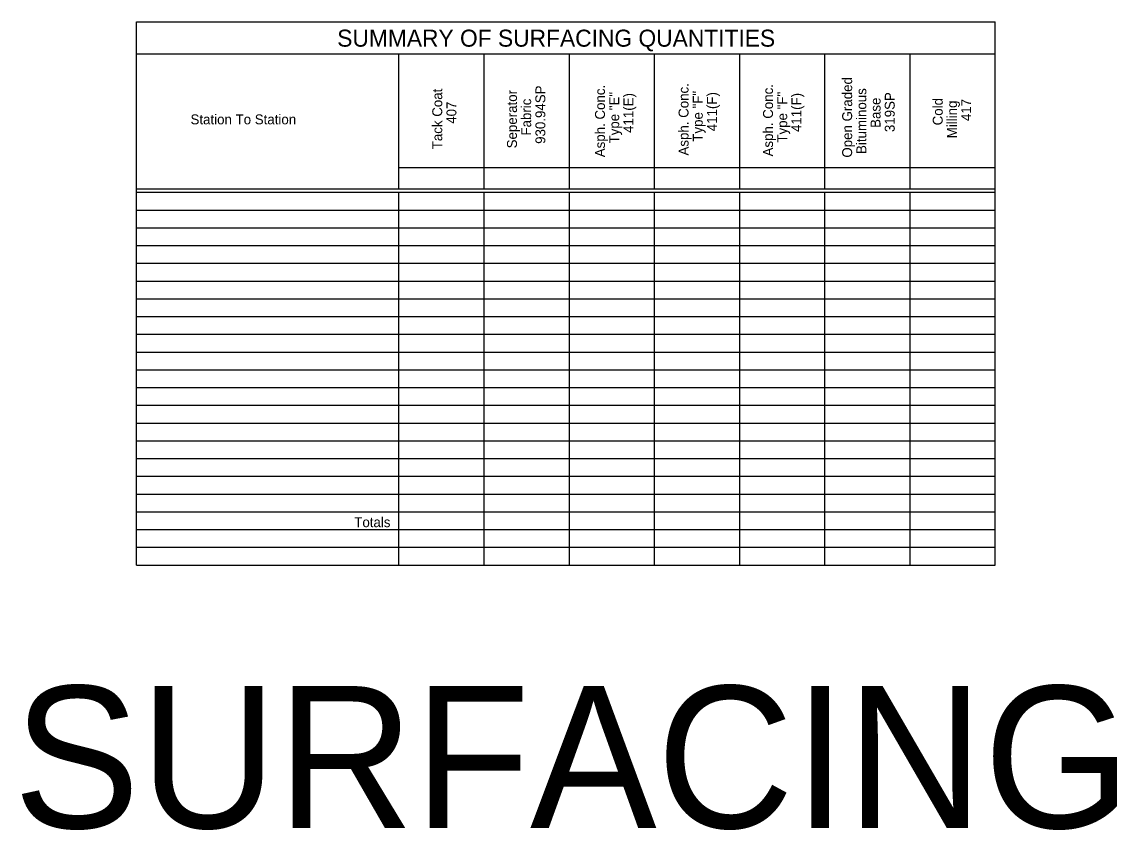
# Model space of a CAD drawing. Extents: x 1790274 to 1791453, y 1790011 to 1790884.
# Drawn here: x 1791298.7 to 1791452.9, y 1790276.5 to 1790390.3 of the extents above; entities that cross this region are included whole.
import ezdxf

# ---------------------------------------------------------------- set-up
doc = ezdxf.new("R2010")
doc.units = 0
doc.layers.add('Level 1', color=7, linetype='Continuous')
doc.layers.add('Level 2', color=7, linetype='Continuous')

msp = doc.modelspace()

# ---------------------------------------------------------------- linework, layer by layer
at = {"layer": 'Level 1'}
for p, q in [((1791314.78, 1790390.3), (1791435.78, 1790390.3)), ((1791314.78, 1790313.8), (1791314.78, 1790390.3)), ((1791435.78, 1790313.8), (1791435.78, 1790390.3)), ((1791314.78, 1790385.8), (1791435.78, 1790385.8)), ((1791351.78, 1790366.8), (1791351.78, 1790385.8)), ((1791363.78, 1790366.8), (1791363.78, 1790385.8)), ((1791375.78, 1790366.8), (1791375.78, 1790385.8)), ((1791387.78, 1790366.8), (1791387.78, 1790385.8)), ((1791399.78, 1790366.8), (1791399.78, 1790385.8)), ((1791411.78, 1790366.8), (1791411.78, 1790385.8)), ((1791423.78, 1790366.8), (1791423.78, 1790385.8)), ((1791351.78, 1790369.8), (1791435.78, 1790369.8)), ((1791314.78, 1790366.8), (1791435.78, 1790366.8)), ((1791314.78, 1790366.3), (1791435.78, 1790366.3)), ((1791351.78, 1790313.8), (1791351.78, 1790366.3)), ((1791363.78, 1790313.8), (1791363.78, 1790366.3)), ((1791375.78, 1790313.8), (1791375.78, 1790366.3)), ((1791387.78, 1790313.8), (1791387.78, 1790366.3)), ((1791399.78, 1790313.8), (1791399.78, 1790366.3)), ((1791411.78, 1790313.8), (1791411.78, 1790366.3)), ((1791423.78, 1790313.8), (1791423.78, 1790366.3)), ((1791314.78, 1790363.8), (1791435.78, 1790363.8)), ((1791314.78, 1790361.3), (1791435.78, 1790361.3)), ((1791314.78, 1790358.8), (1791435.78, 1790358.8)), ((1791314.78, 1790356.3), (1791435.78, 1790356.3)), ((1791314.78, 1790353.8), (1791435.78, 1790353.8)), ((1791314.78, 1790351.3), (1791435.78, 1790351.3)), ((1791314.78, 1790348.8), (1791435.78, 1790348.8)), ((1791314.78, 1790346.3), (1791435.78, 1790346.3)), ((1791314.78, 1790343.8), (1791435.78, 1790343.8)), ((1791314.78, 1790341.3), (1791435.78, 1790341.3)), ((1791314.78, 1790338.8), (1791435.78, 1790338.8)), ((1791314.78, 1790336.3), (1791435.78, 1790336.3)), ((1791314.78, 1790333.8), (1791435.78, 1790333.8)), ((1791314.78, 1790331.3), (1791435.78, 1790331.3)), ((1791314.78, 1790328.8), (1791435.78, 1790328.8)), ((1791314.78, 1790326.3), (1791435.78, 1790326.3)), ((1791314.78, 1790323.8), (1791435.78, 1790323.8)), ((1791314.78, 1790321.3), (1791435.78, 1790321.3)), ((1791314.78, 1790318.8), (1791435.78, 1790318.8)), ((1791314.78, 1790316.3), (1791435.78, 1790316.3)), ((1791314.78, 1790313.8), (1791435.78, 1790313.8))]:
    msp.add_line(p, q, dxfattribs=at)

# ---------------------------------------------------------------- texts
at = {"layer": 'Level 2'}
for s, height, p in [('SUMMARY OF SURFACING QUANTITIES', 2.4, (1791343.08, 1790386.81)), ('Station To Station', 1.4, (1791322.41, 1790375.87)), ('Totals', 1.4, (1791345.48, 1790319.13)), ('SURFACING', 20, (1791297.44, 1790276.75))]:
    msp.add_text(s, height=height, dxfattribs=at).set_placement(p)
for s, p in [('Open Graded', (1791415.62, 1790371.18)), ('Tack Coat', (1791357.87, 1790372.36)), ('Seperator', (1791368.4, 1790372.49)), ('930.94SP', (1791372.4, 1790373.12)), ('Asph. Conc.', (1791380.8, 1790371.24)), ('Type "E"', (1791382.8, 1790373.18)), ('Asph. Conc.', (1791392.57, 1790371.48)), ('Type "F"', (1791394.57, 1790373.43)), ('411(F)', (1791396.57, 1790374.9)), ('Asph. Conc.', (1791404.47, 1790371.35)), ('Type "F"', (1791406.47, 1790373.3)), ('Bituminous', (1791417.62, 1790371.7)), ('319SP', (1791421.62, 1790374.78)), ('407', (1791359.87, 1790375.95)), ('Fabric', (1791370.4, 1790374.29)), ('411(E)', (1791384.8, 1790374.66)), ('411(F)', (1791408.47, 1790374.78)), ('Base', (1791419.62, 1790375.37)), ('Cold', (1791428.38, 1790375.73)), ('Milling', (1791430.38, 1790373.91)), ('417', (1791432.38, 1790376.33))]:
    msp.add_text(s, height=1.4, rotation=90, dxfattribs=at).set_placement(p)

doc.saveas('drawing.dxf')
